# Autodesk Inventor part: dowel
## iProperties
Created: 2005-11
Part Number: dowel
Document SubType Name: Modeling
Designer: Administrator
Manufacturer: Standard
Standards Organization: Custom
Author: Administrator
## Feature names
1. Revolution1
2. Fillet1
